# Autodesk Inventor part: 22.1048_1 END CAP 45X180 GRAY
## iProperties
Created: 2007-01
Part Number: 22.1048_1 END CAP 45X180 GRAY
Document SubType Name: Modeling
Designer: Andy Moles
Material: ABS Plastic
Density: 1.06 g/cm^3
Author: Andy Moles
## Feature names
1. Extrusion1
2. Fillet1
3. Fillet2
4. Extrusion2
5. Fillet3
6. Mirror1
